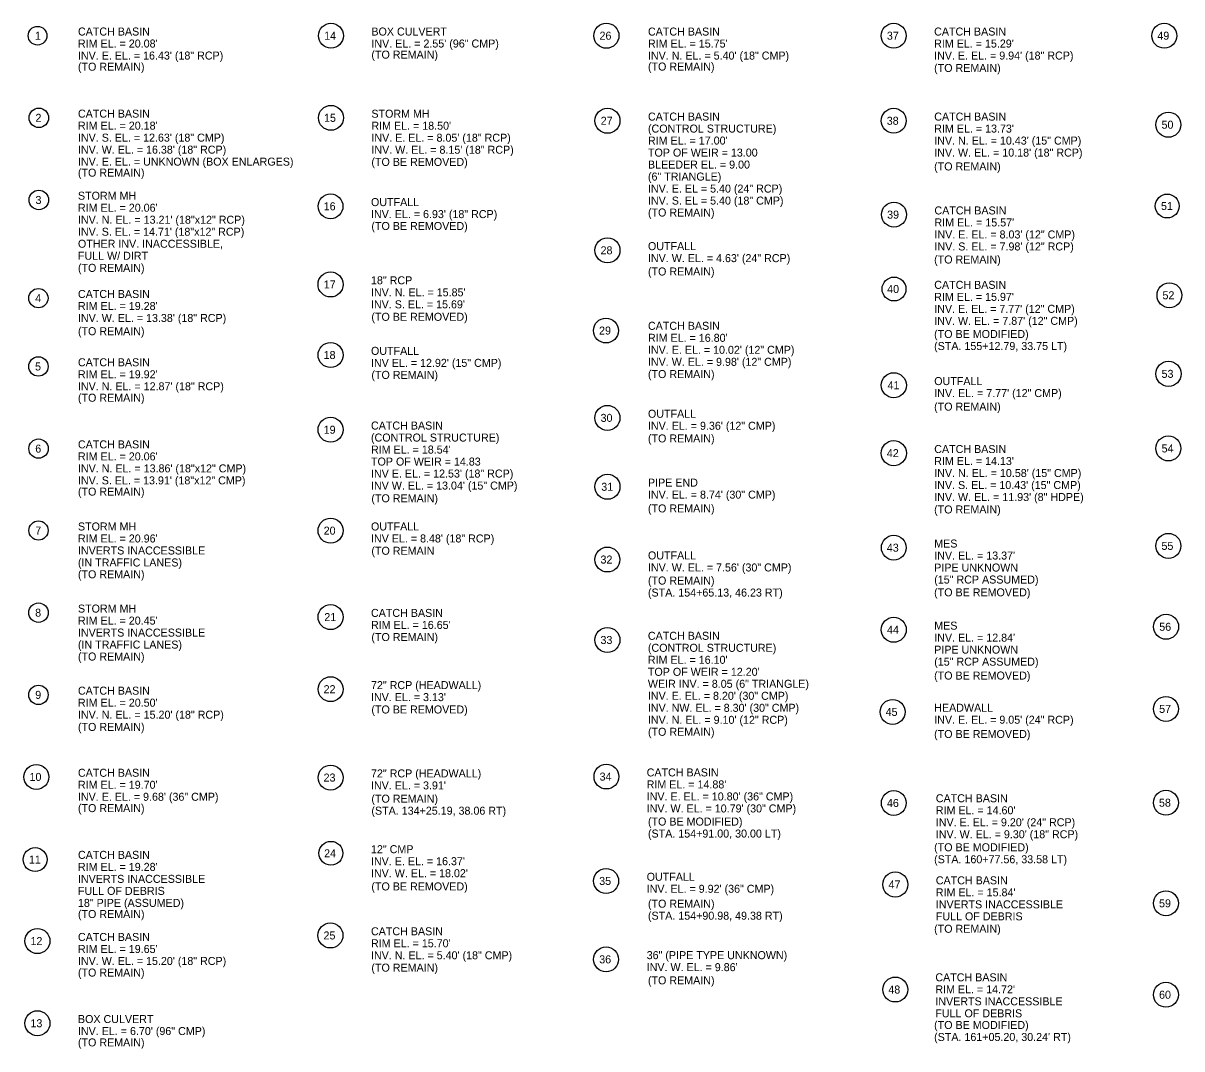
# Model space of a CAD drawing. Extents: x 28 to 1064, y -19 to 515.
# Drawn here: x 28 to 535, y 14 to 463 of the extents above; entities that cross this region are included whole.
import ezdxf

# ---------------------------------------------------------------- set-up
doc = ezdxf.new("R2010")
doc.units = 0
doc.layers.add('TextLabel', color=7, linetype='Continuous')

msp = doc.modelspace()

# ---------------------------------------------------------------- linework, layer by layer
at = {"layer": 'TextLabel'}
for centre, radius in [((34.19, 457.28), 4.08), ((162.52, 457.28), 5.43), ((282.99, 457.28), 5.49), ((408.64, 457.28), 5.47), ((526.97, 457.28), 5.45), ((162.52, 421.36), 5.45), ((34.76, 421.36), 4.26), ((283.47, 420.08), 5.47), ((408.64, 420.08), 5.45), ((528.78, 418.35), 5.49), ((34.76, 385.45), 4.27), ((162.34, 382.67), 5.42), ((528.29, 382.79), 5.22), ((408.78, 379.02), 5.47), ((283.47, 363.41), 5.47), ((162.34, 348.47), 5.48), ((408.79, 346.48), 5.22), ((34.57, 342.48), 4.22), ((529.25, 343.75), 5.43), ((282.79, 328.31), 5.43), ((162.34, 317.61), 5.47), ((34.57, 312.6), 4.25), ((528.85, 309.37), 5.49), ((408.69, 304.39), 5.49), ((283.45, 290.12), 5.47), ((162.34, 284.93), 5.47), ((34.62, 276.67), 4.24), ((408.69, 274.69), 5.49), ((528.79, 276.75), 5.48), ((283.47, 259.97), 5.47), ((34.6, 240.85), 4.21), ((162.34, 240.79), 5.47), ((408.69, 233.34), 5.43), ((528.79, 234.13), 5.47), ((283.45, 228.15), 5.45), ((34.6, 204.92), 4.26), ((162.34, 202.97), 5.47), ((408.69, 197.42), 5.47), ((527.79, 198.74), 5.47), ((283.45, 192.97), 5.47), ((34.6, 168.95), 4.24), ((162.34, 171.44), 5.45), ((527.71, 162.82), 5.45), ((408.15, 161.49), 5.45), ((33.67, 133.07), 5.45), ((162.34, 132.78), 5.45), ((282.99, 133.21), 5.42), ((408.69, 121.66), 5.42), ((527.71, 121.79), 5.45), ((33.12, 96.91), 5.22), ((162.51, 99.66), 5.22), ((282.86, 87.56), 5.48), ((409.36, 86.01), 5.48), ((527.71, 77.78), 5.45), ((34.14, 61.26), 5.49), ((162.29, 63.72), 5.49), ((282.86, 53.27), 5.45), ((409.33, 40.06), 5.45), ((527.71, 37.79), 5.45), ((34.14, 25.32), 5.49)]:
    msp.add_circle(centre, radius, dxfattribs=at)

# ---------------------------------------------------------------- texts
for s, p in [('1', (33.04, 455.53)), ('14', (159.55, 455.53)), ('26', (279.99, 455.53)), ('37', (405.68, 455.53)), ('49', (523.97, 455.53)), ('2', (33.29, 419.61)), ('15', (159.5, 419.61)), ('27', (280.51, 418.33)), ('38', (405.61, 418.33)), ('50', (525.79, 416.6)), ('3', (33.29, 383.7)), ('16', (159.34, 380.92)), ('39', (405.78, 377.27)), ('51', (525.57, 381.04)), ('28', (280.44, 361.66)), ('17', (159.38, 346.72)), ('40', (405.79, 344.73)), ('52', (526.21, 342)), ('4', (33.17, 340.73)), ('29', (279.78, 326.56)), ('18', (159.31, 315.86)), ('5', (33.11, 310.85)), ('53', (525.81, 307.62)), ('41', (405.96, 302.64)), ('30', (280.45, 288.37)), ('19', (159.34, 283.18)), ('6', (33.19, 274.92)), ('42', (405.65, 272.93)), ('54', (525.82, 275)), ('31', (280.75, 258.22)), ('7', (33.21, 239.1)), ('20', (159.34, 239.04)), ('43', (405.65, 231.59)), ('55', (525.77, 232.38)), ('32', (280.41, 226.4)), ('8', (33.14, 203.17)), ('21', (159.61, 201.22)), ('44', (405.72, 195.67)), ('56', (524.79, 196.99)), ('33', (280.4, 191.22)), ('22', (159.31, 169.69)), ('9', (33.17, 167.2)), ('45', (405.13, 159.74)), ('57', (524.75, 161.07)), ('10', (30.68, 131.32)), ('23', (159.3, 131.03)), ('34', (280.02, 131.46)), ('46', (405.69, 119.91)), ('58', (524.68, 120.03)), ('24', (159.54, 97.91)), ('11', (30.4, 95.16)), ('35', (279.84, 85.81)), ('47', (406.4, 84.26)), ('59', (524.71, 76.03)), ('12', (31.1, 59.51)), ('25', (159.26, 61.97)), ('36', (279.86, 51.52)), ('48', (406.31, 38.31)), ('60', (524.71, 36.04)), ('13', (31.09, 23.57))]:
    msp.add_text(s, height=3.5, rotation=0.0168, dxfattribs=at).set_placement(p)
for s, p in [('CATCH BASIN ', (51.86, 457.36)), ('BOX CULVERT', (180.21, 457.36)), ('CATCH BASIN ', (301.17, 457.34)), ('CATCH BASIN', (426.33, 457.35)), ("RIM EL. = 20.08'", (51.86, 452.11)), ('INV. EL. = 2.55\' (96" CMP)', (180.21, 452.11)), ("RIM EL. = 15.75'", (301.17, 452.09)), ("RIM EL. = 15.29'", (426.33, 452.1)), ('INV. E. EL. = 16.43\' (18" RCP)', (51.86, 446.86)), ('(TO REMAIN)', (180.21, 447.26)), ('INV. N. EL. = 5.40\' (18" CMP)', (301.17, 446.84)), ('INV. E. EL. = 9.94\' (18" RCP)', (426.33, 446.85)), ('(TO REMAIN)', (51.86, 441.97)), ('(TO REMAIN)', (301.17, 442.03)), ('(TO REMAIN)', (426.33, 441.42)), ('CATCH BASIN ', (51.86, 421.45)), ('STORM MH ', (180.21, 421.41)), ('CATCH BASIN ', (301.17, 420.16)), ('CATCH BASIN ', (426.38, 420.16)), ("RIM EL. = 20.18'", (51.86, 416.2)), ("RIM EL. = 18.50'", (180.21, 416.16)), ('(CONTROL STRUCTURE)', (301.17, 414.91)), ("RIM EL. = 13.73'", (426.38, 414.91)), ('INV. S. EL. = 12.63\' (18" CMP)', (51.86, 410.95)), ('INV. E. EL. = 8.05\' (18" RCP)', (180.21, 410.91)), ("RIM EL. = 17.00'", (301.17, 409.66)), ('INV. N. EL. = 10.43\' (15" CMP)', (426.38, 409.66)), ('INV. W. EL. = 16.38\' (18" RCP)', (51.86, 405.7)), ('INV. W. EL. = 8.15\' (18" RCP)', (180.21, 405.66)), ('TOP OF WEIR = 13.00', (301.17, 404.41)), ('INV. W. EL. = 10.18\' (18" RCP)', (426.38, 404.41)), ('INV. E. EL. = UNKNOWN (BOX ENLARGES)', (51.86, 400.45)), ('(TO BE REMOVED)', (180.21, 400.34)), ('BLEEDER EL. = 9.00', (301.17, 399.16)), ('(TO REMAIN)', (426.33, 398.35)), ('(TO REMAIN)', (51.86, 395.64)), ('(6" TRIANGLE)', (301.17, 393.91)), ('INV. E. EL = 5.40 (24" RCP)', (301.17, 388.66)), ('STORM MH ', (51.86, 385.54)), ('OUTFALL ', (180.03, 382.75)), ('INV. S. EL = 5.40 (18" CMP)', (301.17, 383.41)), ("RIM EL. = 20.06'", (51.86, 380.29)), ('INV. EL. = 6.93\' (18" RCP)', (180.03, 377.5)), ('(TO REMAIN)', (301.17, 378.2)), ('CATCH BASIN', (426.47, 379.1)), ('INV. N. EL. = 13.21\' (18"x12" RCP)', (51.86, 375.04)), ('(TO BE REMOVED)', (180.21, 372.3)), ("RIM EL. = 15.57'", (426.47, 373.85)), ('INV. S. EL. = 14.71\' (18"x12" RCP)', (51.86, 369.79)), ('INV. E. EL. = 8.03\' (12" CMP)', (426.47, 368.6)), ('OTHER INV. INACCESSIBLE,', (51.86, 364.54)), ('OUTFALL', (301.17, 363.49)), ('INV. S. EL. = 7.98\' (12" RCP)', (426.47, 363.35)), ('FULL W/ DIRT', (51.86, 359.29)), ('INV. W. EL. = 4.63\' (24" RCP)', (301.17, 358.24)), ('(TO REMAIN)', (426.33, 357.64)), ('(TO REMAIN)', (51.86, 353.99)), ('(TO REMAIN)', (301.17, 352.4)), ('18" RCP', (180.03, 348.54)), ('CATCH BASIN ', (426.38, 346.56)), ('CATCH BASIN', (51.86, 342.56)), ("INV. N. EL. = 15.85'", (180.03, 343.29)), ("RIM EL. = 15.97'", (426.38, 341.31)), ("RIM EL. = 19.28'", (51.86, 337.31)), ("INV. S. EL. = 15.69'", (180.03, 338.04)), ('INV. E. EL. = 7.77\' (12" CMP)', (426.38, 336.06)), ('INV. W. EL. = 13.38\' (18" RCP)', (51.86, 332.06)), ('(TO BE REMOVED)', (180.21, 332.58)), ('INV. W. EL. = 7.87\' (12" CMP)', (426.38, 330.81)), ('(TO REMAIN)', (51.86, 326.28)), ('CATCH BASIN ', (301.17, 328.63)), ("RIM EL. = 16.80'", (301.17, 323.38)), ('(TO BE MODIFIED)', (426.33, 325.05)), ('OUTFALL', (180.03, 317.68)), ('INV. E. EL. = 10.02\' (12" CMP)', (301.17, 318.13)), ('(STA. 155+12.79, 33.75 LT)', (426.33, 319.8)), ('CATCH BASIN ', (51.86, 312.68)), ('INV EL. = 12.92\' (15" CMP)', (180.03, 312.43)), ('INV. W. EL. = 9.98\' (12" CMP)', (301.17, 312.88)), ("RIM EL. = 19.92'", (51.86, 307.43)), ('(TO REMAIN)', (180.21, 307.17)), ('(TO REMAIN)', (301.17, 307.53)), ('INV. N. EL. = 12.87\' (18" RCP)', (51.86, 302.18)), ('OUTFALL', (426.38, 304.46)), ('(TO REMAIN)', (51.86, 297.18)), ('INV. EL. = 7.77\' (12" CMP)', (426.38, 299.21)), ('(TO REMAIN)', (426.33, 293.28)), ('OUTFALL', (301.17, 290.17)), ('CATCH BASIN', (180.03, 285.01)), ('INV. EL. = 9.36\' (12" CMP)', (301.17, 284.92)), ('CATCH BASIN ', (51.86, 276.77)), ('(CONTROL STRUCTURE)', (180.03, 279.76)), ('(TO REMAIN)', (301.17, 279.38)), ("RIM EL. = 20.06'", (51.86, 271.52)), ("RIM EL. = 18.54'", (180.03, 274.51)), ('CATCH BASIN', (426.38, 274.74)), ('INV. N. EL. = 13.86\' (18"x12" CMP)', (51.86, 266.27)), ('TOP OF WEIR = 14.83', (180.03, 269.26)), ("RIM EL. = 14.13'", (426.38, 269.49)), ('INV. S. EL. = 13.91\' (18"x12" CMP)', (51.86, 261.02)), ('INV E. EL. = 12.53\' (18" RCP)', (180.03, 264.01)), ('PIPE END', (301.17, 260.05)), ('INV. N. EL. = 10.58\' (15" CMP)', (426.38, 264.24)), ('(TO REMAIN)', (51.86, 256.11)), ('INV W. EL. = 13.04\' (15" CMP)', (180.03, 258.76)), ('INV. EL. = 8.74\' (30" CMP)', (301.17, 254.8)), ('INV. S. EL. = 10.43\' (15" CMP)', (426.38, 258.99)), ('(TO REMAIN)', (180.21, 253.19)), ('INV. W. EL. = 11.93\' (8" HDPE)', (426.38, 253.74)), ('(TO REMAIN)', (301.17, 248.76)), ('(TO REMAIN)', (426.33, 248.3)), ('STORM MH ', (51.86, 240.86)), ('OUTFALL', (180.03, 240.87)), ("RIM EL. = 20.96'", (51.86, 235.61)), ('INV EL. = 8.48\' (18" RCP)', (180.03, 235.62)), ('INVERTS INACCESSIBLE', (51.86, 230.36)), ('(TO REMAIN', (180.21, 230.24)), ('MES', (426.38, 233.4)), ('(IN TRAFFIC LANES)', (51.86, 225.11)), ('OUTFALL ', (301.17, 228.19)), ("INV. EL. = 13.37'", (426.38, 228.15)), ('(TO REMAIN)', (51.86, 219.95)), ('INV. W. EL. = 7.56\' (30" CMP)', (301.17, 222.94)), ('PIPE UNKNOWN', (426.38, 222.9)), ('(TO REMAIN)', (301.17, 217.21)), ('(15" RCP ASSUMED)', (426.38, 217.65)), ('(STA. 154+65.13, 46.23 RT)', (301.17, 211.96)), ('(TO BE REMOVED)', (426.33, 212.05)), ('STORM MH ', (51.86, 204.95)), ("RIM EL. = 20.45'", (51.86, 199.7)), ('CATCH BASIN', (180.03, 203.05)), ('INVERTS INACCESSIBLE', (51.86, 194.45)), ("RIM EL. = 16.65'", (180.03, 197.8)), ('MES', (426.38, 197.49)), ('(IN TRAFFIC LANES)', (51.86, 189.2)), ('(TO REMAIN)', (180.21, 192.5)), ('CATCH BASIN ', (301.14, 193.04)), ("INV. EL. = 12.84'", (426.38, 192.24)), ('(TO REMAIN)', (51.86, 183.97)), ('(CONTROL STRUCTURE)', (301.14, 187.79)), ('PIPE UNKNOWN', (426.38, 186.99)), ("RIM EL. = 16.10'", (301.14, 182.54)), ('(15" RCP ASSUMED)', (426.38, 181.74)), ("TOP OF WEIR = 12.20'", (301.14, 177.29)), ('(TO BE REMOVED)', (426.33, 175.65)), ('CATCH BASIN', (51.86, 169.04)), ('72" RCP (HEADWALL)', (180.03, 171.47)), ('WEIR INV. = 8.05 (6" TRIANGLE)', (301.14, 172.04)), ("RIM EL. = 20.50'", (51.86, 163.79)), ("INV. EL. = 3.13'", (180.03, 166.22)), ('INV. E. EL. = 8.20\' (30" CMP)', (301.14, 166.79)), ('INV. N. EL. = 15.20\' (18" RCP)', (51.86, 158.54)), ('(TO BE REMOVED)', (180.21, 160.81)), ('INV. NW. EL. = 8.30\' (30" CMP)', (301.14, 161.54)), ('HEADWALL', (426.38, 161.58)), ('INV. N. EL. = 9.10\' (12" RCP)', (301.14, 156.29)), ('INV. E. EL. = 9.05\' (24" RCP)', (426.38, 156.33)), ('(TO REMAIN)', (51.86, 153.18)), ('(TO REMAIN)', (301.17, 151.06)), ('(TO BE REMOVED)', (426.33, 150.08)), ('CATCH BASIN ', (300.61, 133.28)), ('CATCH BASIN ', (51.86, 133.13)), ('72" RCP (HEADWALL)', (180.03, 132.85)), ("RIM EL. = 19.70'", (51.86, 127.88)), ("INV. EL. = 3.91'", (180.03, 127.6)), ("RIM EL. = 14.88'", (300.61, 128.03)), ('INV. E. EL. = 9.68\' (36" CMP)', (51.86, 122.63)), ('(TO REMAIN)', (180.21, 121.79)), ('INV. E. EL. = 10.80\' (36" CMP)', (300.61, 122.78)), ('CATCH BASIN ', (427.07, 121.98)), ('(TO REMAIN)', (51.86, 117.67)), ('(STA. 134+25.19, 38.06 RT)', (180.21, 116.54)), ('INV. W. EL. = 10.79\' (30" CMP)', (300.61, 117.53)), ("RIM EL. = 14.60'", (427.07, 116.73)), ('(TO BE MODIFIED)', (301.17, 111.79)), ('INV. E. EL. = 9.20\' (24" RCP)', (427.07, 111.48)), ('(STA. 154+91.00, 30.00 LT)', (301.17, 106.54)), ('INV. W. EL. = 9.30\' (18" RCP)', (427.07, 106.23)), ('12" CMP', (180.03, 99.7)), ('(TO BE MODIFIED)', (426.33, 100.54)), ('CATCH BASIN ', (51.86, 97.22)), ("INV. E. EL. = 16.37'", (180.03, 94.45)), ('(STA. 160+77.56, 33.58 LT)', (426.33, 95.29)), ("RIM EL. = 19.28'", (51.86, 91.97)), ("INV. W. EL. = 18.02'", (180.03, 89.2)), ('INVERTS INACCESSIBLE', (51.86, 86.72)), ('(TO BE REMOVED)', (180.21, 83.42)), ('OUTFALL', (300.61, 87.64)), ('CATCH BASIN ', (427.07, 86.07)), ('FULL OF DEBRIS', (51.86, 81.47)), ('INV. EL. = 9.92\' (36" CMP)', (300.61, 82.39)), ("RIM EL. = 15.84'", (427.07, 80.82)), ('18" PIPE (ASSUMED)', (51.86, 76.22)), ('(TO REMAIN)', (301.17, 75.86)), ('INVERTS INACCESSIBLE', (427.07, 75.57)), ('(TO REMAIN)', (51.86, 71.34)), ('(STA. 154+90.98, 49.38 RT)', (301.17, 70.61)), ('FULL OF DEBRIS', (427.07, 70.32)), ('CATCH BASIN ', (180.03, 63.79)), ('(TO REMAIN)', (426.33, 64.9)), ('CATCH BASIN ', (51.86, 61.31)), ("RIM EL. = 15.70'", (180.03, 58.54)), ("RIM EL. = 19.65'", (51.86, 56.06)), ('INV. N. EL. = 5.40\' (18" CMP)', (180.03, 53.29)), ('36" (PIPE TYPE UNKNOWN)', (300.61, 53.35)), ('INV. W. EL. = 15.20\' (18" RCP)', (51.86, 50.81)), ('(TO REMAIN)', (180.21, 47.89)), ("INV. W. EL. = 9.86'", (300.61, 48.1)), ('(TO REMAIN)', (51.86, 45.73)), ('(TO REMAIN)', (301.17, 42.33)), ('CATCH BASIN ', (426.87, 43.65)), ("RIM EL. = 14.72'", (426.87, 38.4)), ('INVERTS INACCESSIBLE ', (426.87, 33.15)), ('FULL OF DEBRIS', (426.87, 27.9)), ('BOX CULVERT ', (51.86, 25.4)), ('(TO BE MODIFIED)', (426.33, 22.81)), ('INV. EL. = 6.70\' (96" CMP)', (51.86, 20.15)), ("(STA. 161+05.20, 30.24' RT)", (426.33, 17.56)), ('(TO REMAIN)', (51.86, 15.18))]:
    msp.add_text(s, height=3.5, dxfattribs=at).set_placement(p)

doc.saveas('drawing.dxf')
